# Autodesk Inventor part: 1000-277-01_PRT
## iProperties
Created: 2007-03
Part Number: 1000-277-01_PRT
Document SubType Name: Modeling
Designer: Andy Moles
Material: Steel
Mass: 5.32321 g
Surface Area: 7.06394 cm^2
Volume: 0.678116 cm^3
Density: 7.85 g/cm^3
Author: Andy Moles
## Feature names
1. Base1
